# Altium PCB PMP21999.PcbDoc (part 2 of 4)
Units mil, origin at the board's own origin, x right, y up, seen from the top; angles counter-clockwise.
Board outline 7450 x 5800 mil, 6 copper layers (Top Layer, Signal Layer 3, Signal Layer 1, Signal Layer 2, Signal Layer 4, Bottom Layer), stack 66 mil thick; 237 components, 96 nets, 712 pads, 268 vias.
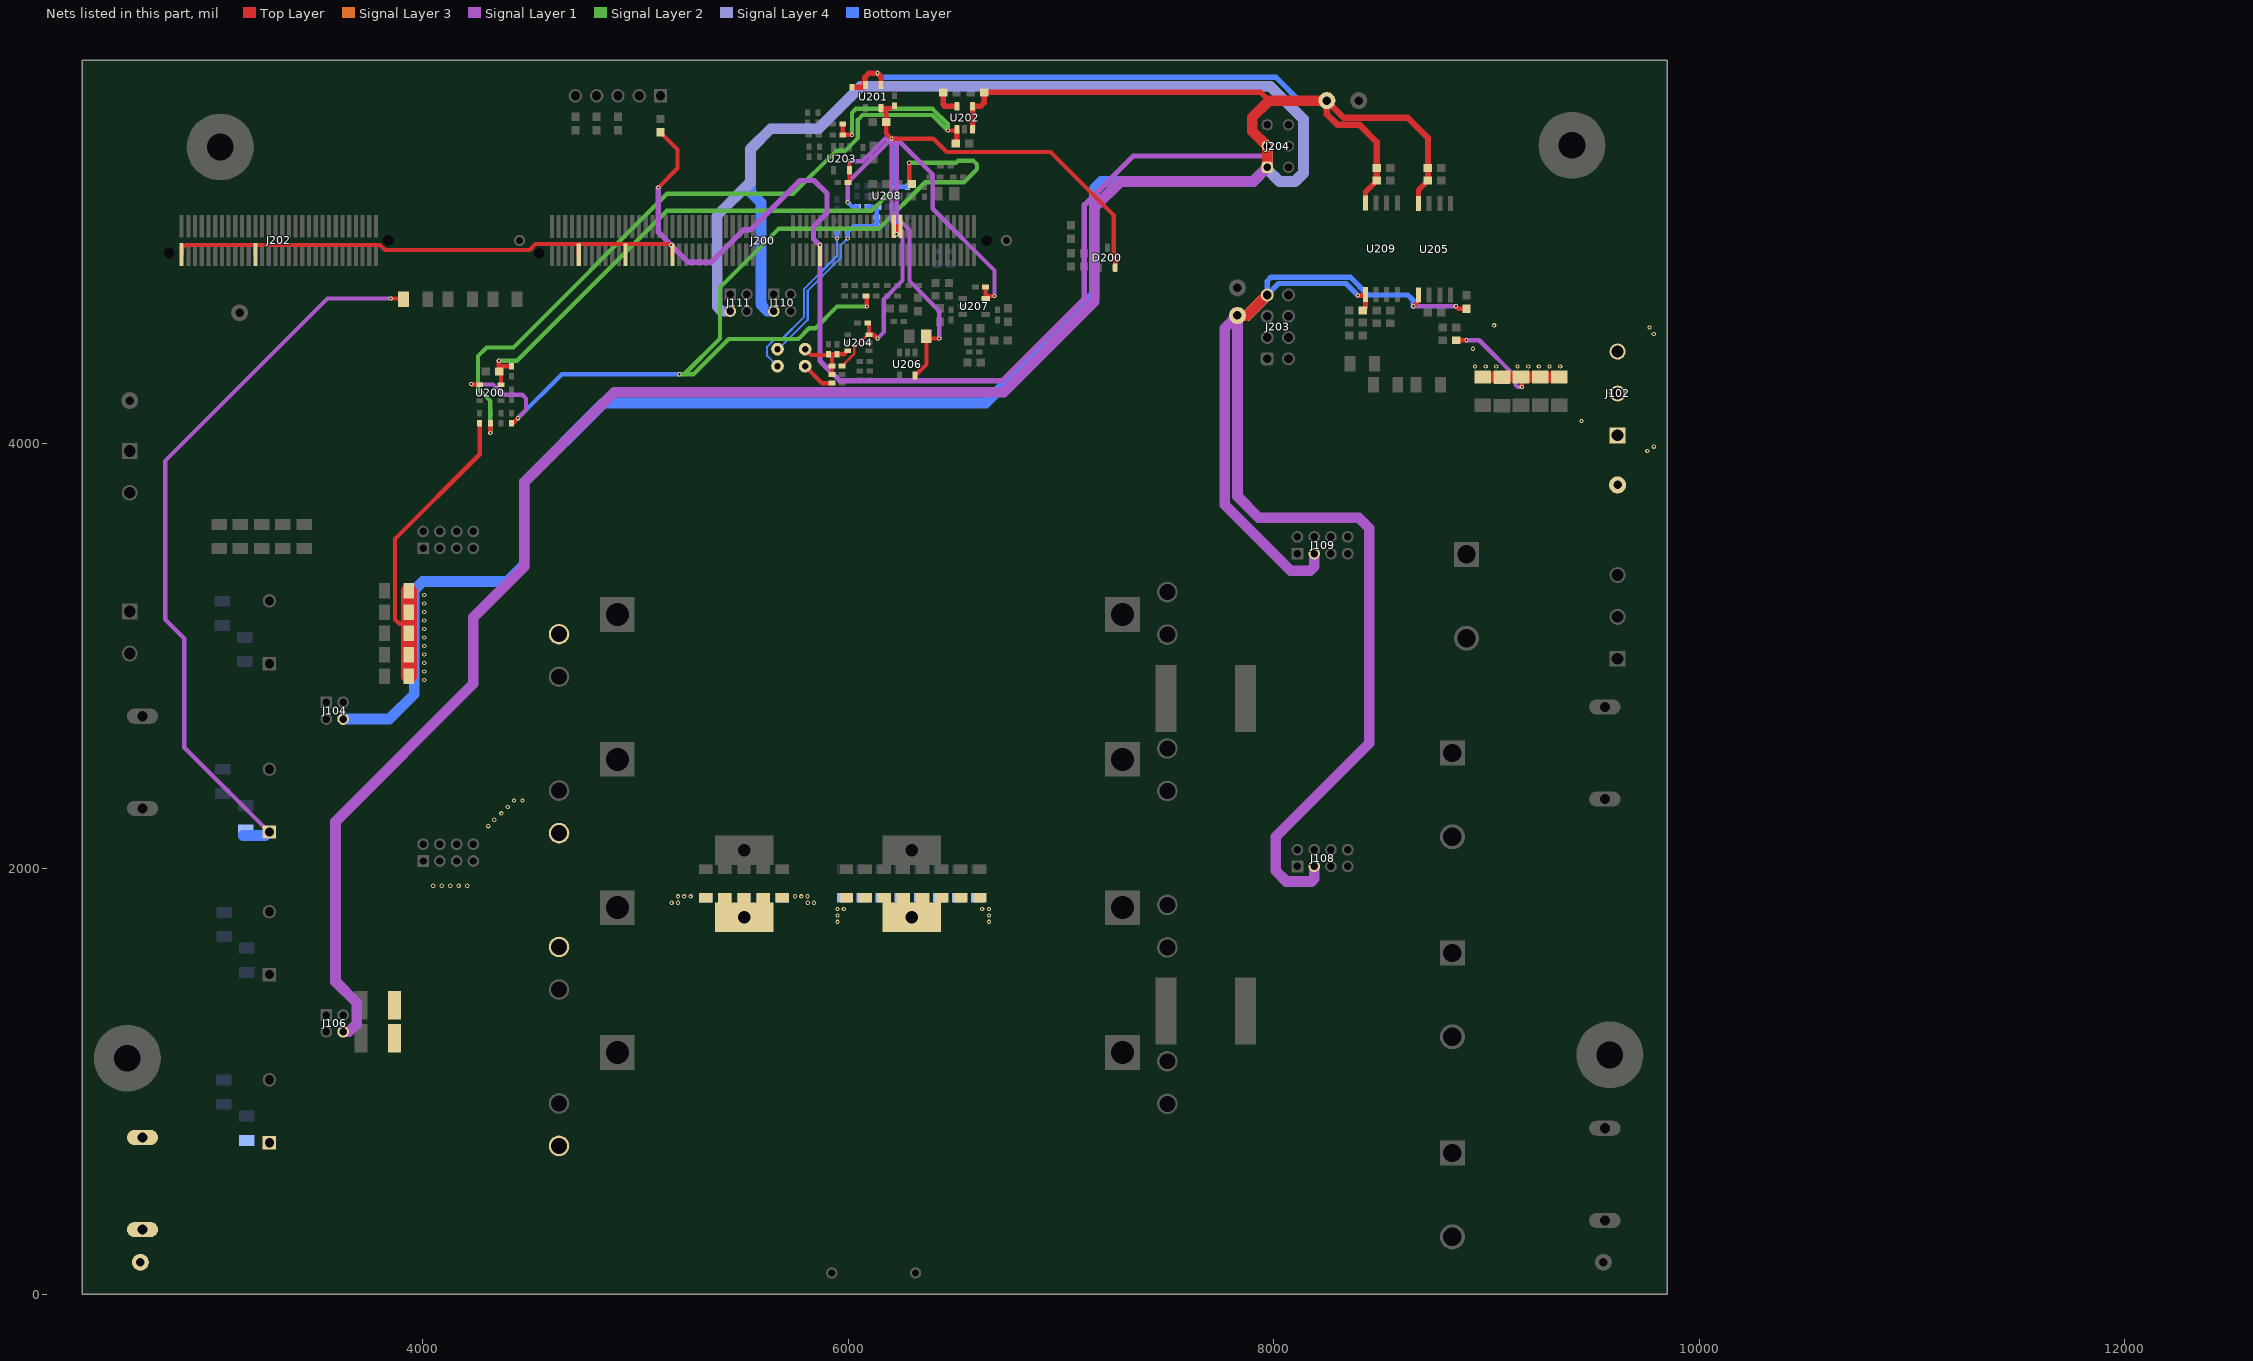
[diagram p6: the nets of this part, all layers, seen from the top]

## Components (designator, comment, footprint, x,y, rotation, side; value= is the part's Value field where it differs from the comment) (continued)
R122 "WSLP1206R0100FEA" 1206 3877.95,3005.51 r0 top value=0.01
R200 "RC0402FR-0756R2L" 0402 6208,4691.87 r180 top value=56.2
R201 "CRCW0402150KFKED" 0402 4418.52,4117.51 r270 top value=150k
R202 "RC0402FR-0756R2L" 0402 6458,5301.87 r180 top value=56.2
R203 "CRCW040210K0FKED" 0402 4418.52,4337.51 r90 top value=10.0k
R204 "CRCW080528K7FKEA" 0805_HV 6458,5171.87 r0 top value=28.7k
R205 "CRCW040210K0FKED" 0402 4268.52,4117.51 r270 top value=10.0k
R206 "CRCW060314K3FKEA" 0603 7048,4991.87 r90 top value=14.3k
R207 "CRCW060325R5FKEA" 0603 6442.41,4692.86 r0 top value=25.5
R208 "CRCW060325R5FKEA" 0603 6328,4651.87 r270 top value=25.5
R209 "RC0402FR-0756R2L" 0402 6518,5251.87 r180 top value=56.2
R210 "CRCW0402150KFKED" 0402 4318.52,4117.51 r90 top value=150k
R211 "CRCW04021K24FKED" 0402 6358,5181.87 r270 top value=1.24k
R212 "CRCW040210K0FKED" 0402 4368.52,4117.51 r90 top value=10.0k
R213 "CRCW040210K0FKED" 0402 4418.52,4227.51 r90 top value=10.0k
R214 "CRCW060356R2FKEA" 0603 6268,5219 r180 top value=56.2
R215 "RC0402FR-0756R2L" 0402 6008,4691.87 r180 top value=56.2
R216 "CRCW06031K00FKEA" 0603 7048,4861.87 r90 top value=1.00k
R217 "RC0402FR-0756R2L" 0402 6108,4691.87 r180 top value=56.2
R218 "CRCW060325R5FKEA" 0603 6148,5219 r180 top value=25.5
R219 "CRCW06030000Z0EA" 0603 5118,5491.87 r270 top value=0
R220 "CRCW06030000Z0EA" 0603 4918,5501.87 r90 top value=0
R221 "CRCW06030000Z0EA" 0603 4818,5501.87 r90 top value=0
R224 "CRCW06030000Z0EA" 0603 4718,5501.87 r90 top value=0
R227 "CRCW06037K15FKEA" 0603 6118.95,5366.13 r90 top value=7.15k
R228 "CRCW04023K65FKED" 0402 6078,4383.53 r180 top value=3.65k
R229 "CRCW040210K0FKED" 0402 5948,4361.87 r0 top value=10.0k
R230 "CRCW04021K00FKED" 0402 5948,4281.87 r0 top value=1.00k
R231 "CRCW04021K00FKED" 0402 6078,4296.87 r0 top value=1.00k
R232 "CRCW060339R2FKEA" 0603 8826.4,4483.54 r180 top value=39.2
R233 "RC0402FR-074K7L" 0402 5808,5529 r270 top value=4.70k
R234 "RC0402FR-074K7L" 0402 5816.35,5369 r270 top value=4.70k
R235 "RC0402FR-074K7L" 0402 5858,5529 r270 top value=4.70k
R236 "RC0402FR-074K7L" 0402 5866.35,5369 r270 top value=4.70k
R237 "CRCW060339R2FKEA" 0603 8826.4,4543.54 r180 top value=39.2
R238 "CRCW04027K15FKED" 0402 5950.87,5449 r180 top value=7.15k
R239 "CRCW040210K0FKED" 0402 5908,4441.87 r270 top value=10.0k
R240 "CRCW1206365KFKEA" 1206 3967.24,4675.42 r180 top value=365k
R241 "RC1206FR-072ML" 1206 8726.4,4273.54 r0 top value=2.00Meg
R242 "CRCW06038K25FKEA" 0603 6752.41,4602.86 r90 top value=8.25k
R243 "CRCW1206365KFKEA" 1206 4177.24,4675.42 r180 top value=365k
R244 "CRCW04023K65FKED" 0402 6088,5183.76 r270 bottom value=3.65k
R245 "RC1206FR-072ML" 1206 8526.4,4273.54 r0 top value=2.00Meg
R246 "CRCW1206365KFKEA" 1206 4387.24,4675.42 r180 top value=365k
R247 "CRCW040210K0FKED" 0402 6068,5111.87 r180 bottom value=10.0k
R248 "CRCW04021K00FKED" 0402 5948,5021.87 r90 bottom value=1.00k
R249 "CRCW04021K00FKED" 0402 5948,5121.87 r90 bottom value=1.00k
R250 "RC1206FR-072ML" 1206 8416.4,4373.54 r0 top value=2.00Meg
R251 "CRCW06030000Z0EA" 0603 8386.4,4566.34 r0 top value=0
R252 "CRCW06032K55FKEA" 0603 6718,4481.87 r180 top value=2.55k
R253 "CRCW06032K55FKEA" 0603 6622.41,4509.1 r90 top value=2.55k
R254 "RC0402FR-0756R2L" 0402 6258,5062.23 r0 bottom value=56.2
R255 "CRCW06035K49FKEA" 0603 6228,4631.87 r180 top value=5.49k
R256 "CRCW06032K55FKEA" 0603 6592.41,4378.6 r180 top value=2.55k
R257 "CRCW06032K55FKEA" 0603 6562.41,4509.1 r90 top value=2.55k
R258 "CRCW060325K5FKEA" 0603 8386.4,4506.34 r180 top value=25.5k
R259 "CRCW06030000Z0EA" 0603 8516.4,4563.54 r180 top value=0
R260 "CRCW06038K25FKEA" 0603 6432.41,4602.86 r270 top value=8.25k
R261 "CRCW040210K0FKED" 0402 6158,5020.06 r180 bottom value=10.0k
T100 "VA-18191B" FP-VA-18191B_XFMR_PTH_8-MFG 6102.36,2165.35 r270 top
TP100 "5000" Keystone5000 2673.46,150 r90 top
TP101 "5000" Keystone5000 9550,150 r90 top
TP102 "5001" Keystone5001 7830,4730 r0 top
TP103 "5001" Keystone5001 9616.4,3803.54 r90 top
TP104 "5001" Keystone5001 2623.46,4200 r90 top
TP105 "5001" Keystone5001 3140,4612.8 r90 top
TP106 "5001" Keystone5001 8400,5610 r0 top
TP200 "5000" Keystone5000 8250,5610 r0 top
TP201 "5000" Keystone5000 7830,4600 r0 top
U200 "LMV116MF" DBV0006A_L 4318.52,4237.51 r0 top
U201 "TLV71333PQDBVRQ1" DBV0005A_N 6118,5629 r270 top
U202 "REF2033AIDDCR" DDC0005A_N 6548,5529 r90 top
U203 "OPA320AIDBVR" DBV0005A_N 5968.95,5336.13 r270 top
U204 "LMV116MF" DBV0006A_L 6048,4471.87 r0 top
U205 "AMC1302QDWVRQ1" DWV0008A 8755.89,4911.57 r90 top
U206 "OPA320AIDBVR" DBV0005A_N 6278,4371.87 r270 top
U207 "OPA320AIDBVR" DBV0005A_N 6592.41,4642.86 r0 top
U208 "LMV116MF" DBV0006A_L 6182.45,5161.87 r90 bottom
U209 "AMC1311BDWVR" DWV0008A 8506.4,4913.54 r90 top
XF100 "1A3400-10" Eaton_1A3400-10 2683.46,2500 r90 top
XF101 "1A3400-10" Eaton_1A3400-10 2683.46,520 r90 top
XF102 "1A3400-10" Eaton_1A3400-10 9556.4,563.54 r270 top
XF103 "1A3400-10" Eaton_1A3400-10 9556.4,2543.54 r270 top

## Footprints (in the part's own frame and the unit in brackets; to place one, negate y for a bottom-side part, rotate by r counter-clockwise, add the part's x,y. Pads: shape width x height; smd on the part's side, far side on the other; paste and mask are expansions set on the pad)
0402 [mm] "0402 from SM-752 data"
  rect 0.8x0.6 smd: 1(-0.6,0) 2(0.6,0)
  silkscreen extent -1.22,-0.52 1.22,0.52, body extent -0.55,-0.3 0.55,0.3, height 0.6
0603 [mm] "0603 from SM-752 data"
  rect 1x0.95 smd: 1(-0.8,0) 2(0.8,0)
  silkscreen extent -1.52,-0.69 1.52,0.69, body extent -0.87,-0.47 0.87,0.47, height 1
0805_HV [mil] "0805 with 30mil clearance between pads"
  rect 50x63 smd: 1(-40,0) 2(40,0)
  silkscreen extent -74,-40 74,40, body extent -43,-29 43,29, height 57
1206 [mm] "1206 from SM-752 data"
  rect 1.3x1.85 smd: 1(-1.45,0) 2(1.45,0)
  silkscreen extent -2.4,-1.21 2.4,1.21, body extent -1.7,-0.9 1.7,0.9, height 1.35
1206_190 [mm] "1206_190"
  rect 1.1x1.6 smd: 1(-1.7,0) 2(1.7,0)
  silkscreen extent -0.9,-1 0.9,1, body extent -1.75,-0.95 1.75,0.95, height 1.9
1812_254 [mm] "SMD, 2-Leads, Body 4.8x3.4mm"
  rect 1.6x3.4 smd: 1(-2,0) 2(2,0)
  silkscreen extent -0.8,-1.7 0.8,1.7, body extent -2.4,-1.7 2.4,1.7, height 2.54
B58031I_1084x785x450 [mm] "SMD, 2-Leads, Body 6.84x7.85mm"
  rect 2.5x8 smd: 1(-4.75,0) 2(4.75,0)
  silkscreen extent -3.2,-3.92 3.2,3.93, body extent -5.67,-4.17 5.67,4.18, height 4.5
CAPRD1000W60D900H1200 [mm] "Disk, Radial Capacitor"
  round 1.35 hole 0.85: 1(-5,0) 2(5,0)
  silkscreen extent -5.3,-3.5 5.3,3.5, body extent -4.48,-3.5 4.48,3.5, height 11.99
controlCARD-120HSEC [mm] "Pads are not numbered according to Samtec datasheet."
  rect 0.5x2.724 smd: 1(-23.357,-1.678) 2(-23.357,1.722) 3(-22.557,-1.678) 4(-22.557,1.722) 5(-21.757,-1.678) 6(-21.757,1.722) 7(-20.957,-1.678) 8(-20.957,1.722) 9(-20.157,-1.678) 10(-20.157,1.722) 11(-19.357,-1.678) 12(-19.357,1.722) 13(-18.557,-1.678) 14(-18.557,1.722) 15(-17.757,-1.678) 16(-17.757,1.722) 17(-16.957,-1.678) 18(-16.957,1.722) 19(-16.157,-1.678) 20(-16.157,1.722) 21(-15.357,-1.678) 22(-15.357,1.722) 23(-14.557,-1.678) 24(-14.557,1.722) 25(-13.757,-1.678) 26(-13.757,1.722) 27(-12.957,-1.678) 28(-12.957,1.722) 29(-12.157,-1.678) 30(-12.157,1.722) 31(-11.357,-1.678) 32(-11.357,1.722) 33(-10.557,-1.678) 34(-10.557,1.722) 35(-9.757,-1.678) 36(-9.757,1.722) 37(-8.957,-1.678) 38(-8.957,1.722) 39(-8.157,-1.678) 40(-8.157,1.722) 41(-7.357,-1.678) 42(-7.357,1.722) 43(-6.557,-1.678) 44(-6.557,1.722) 45(-5.757,-1.678) 46(-5.757,1.722) 47(-4.957,-1.678) 48(-4.957,1.722) 49(-4.157,-1.678) 50(-4.157,1.722) 51(-3.357,-1.678) 52(-3.357,1.722) 53(-2.557,-1.678) 54(-2.557,1.722) 55(-1.757,-1.678) 56(-1.757,1.722) 57(2.243,-1.678) 58(2.243,1.722) 59(3.043,-1.678) 60(3.043,1.722) 61(3.843,-1.678) 62(3.843,1.722) 63(4.643,-1.678) 64(4.643,1.722) 65(5.443,-1.678) 66(5.443,1.722) 67(6.243,-1.678) 68(6.243,1.722) 69(7.043,-1.678) 70(7.043,1.722) 71(7.843,-1.678) 72(7.843,1.722) 73(8.643,-1.678) 74(8.643,1.722) 75(9.443,-1.678) 76(9.443,1.722) 77(10.243,-1.678) 78(10.243,1.722) 79(11.043,-1.678) 80(11.043,1.722) 81(11.843,-1.678) 82(11.843,1.722) 83(12.643,-1.678) 84(12.643,1.722) 85(13.443,-1.678) 86(13.443,1.722) 87(14.243,-1.678) 88(14.243,1.722) 89(15.043,-1.678) 90(15.043,1.722) 91(15.843,-1.678) 92(15.843,1.722) 93(16.643,-1.678) 94(16.643,1.722) 95(17.443,-1.678) 96(17.443,1.722) 97(18.243,-1.678) 98(18.243,1.722) 99(19.043,-1.678) 100(19.043,1.722) 101(19.843,-1.678) 102(19.843,1.722) 103(20.643,-1.678) 104(20.643,1.722) 105(21.443,-1.678) 106(21.443,1.722) 107(22.243,-1.678) 108(22.243,1.722) 109(23.043,-1.678) 110(23.043,1.722) 111(23.843,-1.678) 112(23.843,1.722) 113(24.643,-1.678) 114(24.643,1.722) 115(25.443,-1.678) 116(25.443,1.722) 117(26.243,-1.678) 118(26.243,1.722) 119(27.043,-1.678) 120(27.043,1.722)
  round 0.025 hole 1.27 unplated mask+0.876: 181(-24.857,0.022) 182(28.543,1.522)
  round 1.348 hole 0.84: 185(-27.207,0.022) 186(30.893,0.022)
  silkscreen extent -32.11,-3.86 35.8,3.9, body extent -31.75,-3.48 35.3,3.52, height 12.35
controlCARD-180HSEC-60pinAddon [mm] "Pads are not numbered according to datasheet."
  round 0.025 hole 1.27 unplated mask+0.876: 61(-13.1,0) 62(13.1,1.5)
  rect 0.5x2.724 smd: 121(-11.6,-1.7) 122(-11.6,1.7) 123(-10.8,-1.7) 124(-10.8,1.7) 125(-10,-1.7) 126(-10,1.7) 127(-9.2,-1.7) 128(-9.2,1.7) 129(-8.4,-1.7) 130(-8.4,1.7) 131(-7.6,-1.7) 132(-7.6,1.7) 133(-6.8,-1.7) 134(-6.8,1.7) 135(-6,-1.7) 136(-6,1.7) 137(-5.2,-1.7) 138(-5.2,1.7) 139(-4.4,-1.7) 140(-4.4,1.7) 141(-3.6,-1.7) 142(-3.6,1.7) 143(-2.8,-1.7) 144(-2.8,1.7) 145(-2,-1.7) 146(-2,1.7) 147(-1.2,-1.7) 148(-1.2,1.7) 149(-0.4,-1.7) 150(-0.4,1.7) 151(0.4,-1.7) 152(0.4,1.7) 153(1.2,-1.7) 154(1.2,1.7) 155(2,-1.7) 156(2,1.7) 157(2.8,-1.7) 158(2.8,1.7) 159(3.6,-1.7) 160(3.6,1.7) 161(4.4,-1.7) 162(4.4,1.7) 163(5.2,-1.7) 164(5.2,1.7) 165(6,-1.7) 166(6,1.7) 167(6.8,-1.7) 168(6.8,1.7) 169(7.6,-1.7) 170(7.6,1.7) 171(8.4,-1.7) 172(8.4,1.7) 173(9.2,-1.7) 174(9.2,1.7) 175(10,-1.7) 176(10,1.7) 177(10.8,-1.7) 178(10.8,1.7) 179(11.6,-1.7) 180(11.6,1.7)
  silkscreen extent -14.68,-3.88 14.68,3.88, body extent -14.3,-3.5 14.3,3.5, height 7.95
CSNL1206 [mm] "Stackpole Electronics"
  rrect6% 1.6x2 smd: 1(-1.7,0) 2(1.7,0)
  silkscreen extent -0.63,-1.02 0.63,1.05, body extent -1.72,-0.92 1.72,0.92, height 0.9
DBV0005A_N [mm] "SOT23, 5-Leads, Body 2.9x1.6mm, Pitch 0.95mm, Lead Span 2.8mm, IPC Medium Density"
  rrect17% 1x0.6 smd: 1(-1.375,0.95) 2(-1.375,0) 3(-1.375,-0.95) 4(1.375,-0.95) 5(1.375,0.95)
  silkscreen extent -1.63,-1.55 0.38,1.55, body extent -1.42,-1.46 1.42,1.46, height 1.09
DBV0006A_L [mm] "SOT23, 6-Leads, Body 2.9x1.6mm, Pitch 0.95mm, Lead Span 2.8mm, IPC High Density"
  rrect18% 0.8x0.55 smd: 1(-1.275,0.95) 2(-1.275,0) 3(-1.275,-0.95) 4(1.275,-0.95) 5(1.275,0) 6(1.275,0.95)
  silkscreen extent -1.55,-1.53 0.55,1.53, body extent -1.42,-1.46 1.42,1.46, height 1.12
DDC0005A_N [mm]
  rrect17% 1x0.6 smd: 1(-1.375,0.95) 2(-1.375,0) 3(-1.375,-0.95) 4(1.375,-0.95) 5(1.375,0.95)
  silkscreen extent -1.25,-1.52 0.88,1.57, body extent -1.41,-1.45 1.41,1.45, height 1.1
DWV0008A [mm] "SOIC, 8-Leads, Body 5.95x7.6mm (max), Pitch 1.27mm"
  rrect17% 1.8x0.6 smd: 1(-5.45,1.905) 2(-5.45,0.635) 3(-5.45,-0.635) 4(-5.45,-1.905) 5(5.45,-1.905) 6(5.45,-0.635) 7(5.45,0.635) 8(5.45,1.905)
  silkscreen extent -6.25,-2.95 2.98,2.95, body extent -5.77,-2.92 5.77,2.93, height 2.67
Eaton_1A3400-10 [mm] "TH, 2-Leads, Body 11.1x11.94mm"
  oval 1.8x3.75 hole 1.2 slot 2.5 at 90 deg: 1(-5.5,0) 2(5.5,0)
  body extent -5.85,-6.41 5.85,6.41, height 18.03
FC_1600x4000 [mm] "TH, 2-Leads, Dia 16mm, Pin Spacing 7.5mm"
  rect 1.6x1.6 hole 1.1: 1(-3.75,0)
  round 1.6 hole 1.1: 2(3.75,0)
  silkscreen extent -8.25,-8.25 8.25,8.25, body extent -8.19,-8.24 8.23,8.24, height 42.01
FCC_disclaimer [mil]
FP-MTMM-102-09-G-D-315_HDR4-MFG [mm]
  rrect7% 1.39x1.39 hole 0.89 paste-1000 mask+0: 1(-1,-1)
  round 1.39 hole 0.89 paste-1000 mask+0: 2(-1,1) 3(1,-1) 4(1,1)
  body extent -2.1,-2.09 2.1,2.09, height 0.25
FP-MTMM-104-09-G-D-320_HDR8-MFG [mm]
  rrect7% 1.39x1.39 hole 0.89 paste-1000 mask+0: 1(-3,-1)
  round 1.39 hole 0.89 paste-1000 mask+0: 2(-3,1) 3(-1,-1) 4(-1,1) 5(1,-1) 6(1,1) 7(3,-1) 8(3,1)
  body extent -4.1,-2.13 4.1,2.13, height 0.25
FP-VA-18191B_XFMR_PTH_8-MFG [mm]
  rect 4.15x4.15 hole 2.75 square paste-1000 mask+0: 1(-26.15,-30.15) 2(26.15,-30.15) 3(-8.85,30.15) 4(8.85,30.15) 5(-8.85,-30.15) 6(8.85,-30.15) 7(-26.15,30.15) 8(26.15,30.15)
  body extent -49.6,-33.35 49.6,33.35, height 0.25
IEC_HighVoltage_Medium [mil]
  silkscreen extent -217,-176 217,200
IEC_HotSurface_Medium [mil]
  silkscreen extent -217,-188 217,188
Keystone5000 [mil] "For Keystone 500x miniature loop terminals"
  round 80 hole 40: 1(0,0)
  silkscreen extent -52,-52 52,52, body extent -49,-49 49,49, height 182
Keystone5001 [mil] "For Keystone 500x miniature loop terminals"
  round 80 hole 40: 1(0,0)
  silkscreen extent -52,-52 52,52, body extent -49,-49 49,49, height 182
Keystone_1902C [mil] "Hex Standoff, 4-40 threaded, nylon"
  round 1 on Mech4: 0(0,0)
  body extent -145,-126 146,126, height 501
Mill-Max_0312-0-15-15-34-27-10-0 [mm] "Pin Receptacle, .032-.046\" .075\" Dia, Gold, TH"
  round 2.45 hole 1.905: 1(0,0)
  silkscreen extent -1.52,-1.52 1.52,1.52, body extent -1.15,-1.15 1.16,1.15, height 0.46
Nichicon_2200x4500_Snap [mm]
  rrect3% 3x3 hole 2.2: 1(-5,0)
  round 3 hole 2.2: 2(5,0)
  silkscreen extent -11.6,-11.6 11.6,11.6, body extent -11.5,-11.49 11.51,11.49, height 47.01
"NY PMS 440 0025 PH" [mm] "4-40 nylon screw and mounting hole"
  round 8 hole 3.2: 1(0,0)
  body extent -3.3,-3.3 3.3,3.3, height 2.69
Pb-Free_Overlay_Medium [mil]
  silkscreen extent -95,-95 95,95
Samtec_SSW-104-24-x-D [mm] "Receptacle, 2.54mm, 4x2, TH"
  rrect50% 1.55x1.55 hole 1.04: 1(-3.81,1.27)
  round 1.55 hole 1.04: 2(-3.81,-1.27) 3(-1.27,1.27) 4(-1.27,-1.27) 5(1.27,1.27) 6(1.27,-1.27) 7(3.81,1.27) 8(3.81,-1.27)
  silkscreen extent -5.43,-2.58 5.43,3, body extent -5.33,-2.48 5.33,2.48, height 8.51
SOT-23 [mm] "SOT23, 3-Leads, Body 2.9x1.3mm, Pitch 0.95mm, Lead Span 2.5mm, IPC Medium Density"
  rrect50% 1x0.6 smd: 1(-1.2,0.95) 2(-1.2,-0.95) 3(1.2,0)
  silkscreen extent -1.62,-1.5 0.7,1.5, body extent -1.16,-1.45 1.21,1.45, height 1
TE_215307-3 [mm] "Receptacle, 2.54mm, 3x2, TH"
  rrect50% 1.35x1.35 hole 0.9: 1(-2.54,1.27)
  round 1.35 hole 0.9: 2(-2.54,-1.27) 3(0,1.27) 4(0,-1.27) 5(2.54,1.27) 6(2.54,-1.27)
  body extent -3.81,-2.53 3.81,2.53, height 7
TE_282856-2 [mm] "TH, 2-Leads, Body 10x10mm, Pitch 5mm"
  rect 1.9x1.9 hole 1.4: 1(-2.5,0)
  round 1.9 hole 1.4: 2(2.5,0)
  silkscreen extent -5.61,-5 5.5,5, body extent -5,-5 5.5,5, height 19
TE_282856-3 [mm] "Receptacle, 3x1, 5mm, R/A, TH"
  rect 1.9x1.9 hole 1.4: 1(-5,0)
  round 1.9 hole 1.4: 2(0,0) 3(5,0)
  silkscreen extent -8,-5 8,5, body extent -7.5,-5 8,5, height 19
WEEE_Minimum [mil] "WEEElie bin"
  silkscreen extent -95,-172 99,104
Wurth_61300511021 [mm] "Header, 2.54 mm, 5x1, R/A, TH"
  rect 1.6x1.6 hole 1.1: 1(-5.08,0)
  round 1.6 hole 1.1: 2(-2.54,0) 3(0,0) 4(2.54,0) 5(5.08,0)
  silkscreen extent -6.75,-4.04 6.35,-1.5, body extent -6.35,-10.04 6.35,0.32, height 2.55

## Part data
C100 C105 C108 C109 C110 C113 C114 C115 C122 C126 C127 C128 C129 C130 C131 C132 C133 C134 C135 C136 C137 C138 C139 C141 C143 C145: library part CMP-0008795-2, "CAP CER 8200PF 630V NP0 1206", Cap_Case=1206, Manufacturer=TDK, PartNumber=CGA5L4NP02J822J160AA, TempCo=C0G, Tolerance_%=5%, Value1=Unknown, Value2=630V, ValueDisplayed=8200pF
C101 C102 C111 C112: library part EEU-FC2A471, "CAP ALUM 150UF 20% 400V RADIAL", Cap_Case=16x40mm, Manufacturer=Rubycon, Tolerance_%=20, Value2=400V, ValueDisplayed=150µF
C103 C104 C106 C107: library part LLS2G221MELZ, "CAP ALUM 150UF 20% 500V SNAP", Cap_Case=22x45mm, Manufacturer=Rubycon, Tolerance_%=20, Value2=500V, ValueDisplayed=150µF
C120: library part C1812W104KDRACTU, "CAP, CERM, 0.1 µF, 1000 V,+/- 10%, X7R, 1812", Cap_Case=1812, Manufacturer="Knowles Syfer", TempCo=X7R, Tolerance_%=10, Value2=1000V, ValueDisplayed=0.1µF
C121: library part C1812W104KDRACTU, "CAP CER 0.1UF 1KV X7R 1812", Cap_Case=1812, Manufacturer="Knowles Syfer", TempCo=X7R, Tolerance_%=10, Value2=1000V, ValueDisplayed=0.1µF
C123 C124: library part CMP-0009311-2, "CAP, CERM, 1 uF, 500 V, +/- 20%, B58031, AEC-Q200 Grade 0, 6.84x7.85mm", Cap_Case=10.84x7.85x4.5mm, Manufacturer=TDK, PartNumber=B58031I5105M062, TempCo=B58031, Tolerance_%=20%, Value1=Unknown, Value2=500V, ValueDisplayed=1uF
C147: "CAP, CERM, 2200 pF, 250 V, +/- 20%, E, Cap, 7x12x9 mm", Cap_Case=CAPRD1000W60D900H1200, Manufacturer=MuRata, Supplier Part Number 1=490-7047-ND, TempCo=E, Tolerance_%=20, Value1=Unknown, Value2=250V, ValueDisplayed=2200pF
C200 C210 C211 C246: "CAP, CERM, 10 pF, 10 V,+/- 2.5%, C0G/NP0, 0402", Cap_Case=0402, Manufacturer=Kemet, Supplier Part Number 1=399-8939-1-ND, TempCo=C0G/NP0, Tolerance_%=2.5, Value2=10V, ValueDisplayed=10pF
C201 C205 C206 C209 C216 C218 C219 C224 C237: "CAP, CERM, 0.1uF, 25V, +/-5%, X7R, 0603", Cap_Case=0603, Manufacturer=AVX, Supplier Part Number 1=478-3713-1-ND, TempCo=X7R, Tolerance_%=5, Value1="0.05 ohm", Value2=25V, ValueDisplayed=0.1µF
C202: "CAP, CERM, 2.2 µF, 6.3 V,+/- 10%, X6S, 0603", Cap_Case=0603, Manufacturer=MuRata, Supplier Part Number 1=GRM188C80J225KE19D-ND, TempCo=X6S, Tolerance_%=10, Value2=6.3V, ValueDisplayed=2.2µF
C203: library part GRM155R60J222KA01D, "CAP CER 2200PF 6.3V X7R 0402", Cap_Case=0402, Manufacturer=KEMET, TempCo=X7R, Tolerance_%=10, Value2=6.3V, ValueDisplayed=2200pF
C204: library part GRM1555C1H221JA01D, "CAP, CERM, 220 pF, 50 V,+/- 5%, C0G/NP0, 0402", Cap_Case=0402, Manufacturer=Yageo, TempCo=C0G/NP0, Tolerance_%=5, Value2=50V, ValueDisplayed=220pF
C207 C225 C238: "CAP, CERM, 0.1 µF, 25 V,+/- 20%, X7R, 0402", Cap_Case=0402, Manufacturer=TDK, Supplier Part Number 1=445-7349-1-ND, TempCo=X7R, Tolerance_%=20, Value2=25V, ValueDisplayed=0.1µF
C208: "CAP, CERM, 10 pF, 50 V,+/- 5%, C0G/NP0, 0603", Cap_Case=0603, Manufacturer=Kemet, Supplier Part Number 1=399-1049-1-ND, TempCo=C0G/NP0, Tolerance_%=5, Value2=50V, ValueDisplayed=10pF
C214 C222 C235: "CAP, CERM, 1uF, 25V, +/-10%, X7R, 0603", Cap_Case=0603, Manufacturer=TDK, Supplier Part Number 1=445-5956-1-ND, TempCo=X7R, Tolerance_%=10, Value1=Unknown, Value2=25V, ValueDisplayed=1uF
C215 C217: library part GRM155R70J104KA01D, "CAP, CERM, 0.1uF, 6.3V, +/-10%, X7R, 0402", Cap_Case=0402, Manufacturer=Yageo, TempCo=X7R, Tolerance_%=10, Value1=Unknown, Value2=6.3V, ValueDisplayed=0.1uF
C220 C229 C230 C232 C243 C244: "CAP, CERM, 0.01 µF, 10 V,+/- 10%, X5R, 0402", Cap_Case=0402, Manufacturer=MuRata, Supplier Part Number 1=GRM155R61A103KA01D-ND, TempCo=X5R, Tolerance_%=10, Value2=10V, ValueDisplayed=0.01µF
C221 C233: "CAP, CERM, 2.2 pF, 50 V,+/- 5%, C0G/NP0, 0402", Cap_Case=0402, Manufacturer=MuRata, Supplier Part Number 1=490-6227-1-ND, TempCo=C0G/NP0, Tolerance_%=5, Value2=50V, ValueDisplayed=2.2pF
C223 C236: "CAP, CERM, 4.7 µF, 10 V,+/- 10%, X5R, 0603", Cap_Case=0603, Manufacturer=TDK, Supplier Part Number 1=445-7482-1-ND, TempCo=X5R, Tolerance_%=10, Value2=10V, ValueDisplayed=4.7µF
C226 C231 C239 C245: "CAP, CERM, 0.1 µF, 16 V,+/- 10%, X7R, 0402", Cap_Case=0402, Manufacturer=AVX, Supplier Part Number 1=478-7888-1-ND, TempCo=X7R, Tolerance_%=10, Value2=16V, ValueDisplayed=0.1µF
C227 C240: "CAP, CERM, 2200 pF, 50 V,+/- 10%, X7R, AEC-Q200 Grade 1, 0402", Cap_Case=0402, Manufacturer=TDK, Supplier Part Number 1=445-5606-1-ND, TempCo=X7R, Tolerance_%=10, Value1="1.07794 ohm", Value2=50V, ValueDisplayed=2200pF
C228 C242: "CAP, CERM, 0.01 µF, 100 V,+/- 10%, X7R, 0603", Cap_Case=0603, Manufacturer=AVX, Supplier Part Number 1=478-1205-1-ND, TempCo=X7R, Tolerance_%=10, Value1="0.098 ohm", Value2=100V, ValueDisplayed=0.01µF
C234: "CAP, CERM, 0.1 µF, 25 V,+/- 5%, X7R, 0805", Cap_Case=0805, Manufacturer=AVX, Supplier Part Number 1=478-7946-1-ND, TempCo=X7R, Tolerance_%=5, Value2=25V, ValueDisplayed=0.1µF
C241: "CAP, CERM, 470 pF, 50 V,+/- 10%, X7R, AEC-Q200 Grade 1, 0402", Cap_Case=0402, Manufacturer=TDK, Supplier Part Number 1=445-6888-1-ND, TempCo=X7R, Tolerance_%=10, Value1="4.96489 ohm", Value2=50V, ValueDisplayed=470pF
D200: library part CMP-0028456-1, "Diode, Schottky, 30 V, 0.2 A, SOT-23", Manufacturer="Diodes Inc.", Supplier Part Number 1=BAT54S-FDICT-ND, Value1=0.2A, Value2=0.65V
H200 H202 H204 H206: library part CMP-0003610-1, "Standoff, Hex, 0.5\"L #4-40 Nylon", Manufacturer=Keystone, Supplier Part Number 1=36-1902C-ND
H201 H203 H205 H207: library part CMP-0003617-1, "Machine Screw, Round, #4-40 x 1/4, Nylon, Philips panhead", Manufacturer="B&F Fastener Supply", Supplier Part Number 1=H542-ND
J100 J103: library part CMP-0054978-1, "Therminal Block, 5 mm, 2-pole, Tin, TH", Manufacturer="On Shore Technology Inc.", PartNumber=ED700/2
J101 J102: library part CMP-0054983-1, "Receptacle, 3x1, 5mm, R/A, TH", Color=Green, Current_A=24A, Manufacturer="On Shore Technology Inc.", PartNumber=ED700/3, Voltage_V=300V
J104 J106: library part CMP-0087195-1, "Conn Unshrouded Header HDR 4 POS 2mm Solder ST Thru-Hole", Manufacturer=Samtec
J105 J107 J108 J109: library part CMP-0087215-1, "Conn Unshrouded Header HDR 8 POS 2mm Solder ST Thru-Hole", Manufacturer=Samtec
J110 J111: library part CMP-0087195-1, "Conn Unshrouded Header HDR 4 POS 2mm Solder ST Thru-Hole", Manufacturer=Samtec, PartNumber=MTMM-102-04-G-D-148
J200: library part controlCARD-120HSEC, "C2000 controlCARD-120HSEC connector, SMT", Manufacturer=Samtec
J201: library part CMP-0054800-1, "Header, 2.54 mm, 5x1, Gold, R/A, TH", Color=Black, Manufacturer="Wurth Elektronik", Supplier Part Number 1=732-5338-ND
J202: library part CMP-0003859-2, "C2000 controlCARD-180HSEC (60-pin addon) connector, SMT", Manufacturer=Samtec
J203: library part CMP-0055706-1, "Receptacle, 2.54mm, 4x2, Gold, TH", Color=Black, Current_A=4.7A, Manufacturer=Samtec, Voltage_V=465V
J204: library part CMP-0082603-1, "Receptacle, 2.54mm, 3x2, Tin, TH", Color=Green, Manufacturer="TE Connectivity", Supplier Part Number 1=A106656-ND
LOGO100: library part IEC_HotSurface, "IEC 61010-1 Hot Surface Warning"
Logo101: library part CMP-0074839-1
Logo102: library part CMP-0074847-1, "FCC_disclaimer"
Logo103: library part CMP-0074769-1
LOGO104 LOGO105: library part IEC_HighVoltage, "IEC 61010-1 High Voltage Warning"
QPL1H_D QPL1H_S QPL1L_D QPL1L_S QPL2H_D QPL2H_S QPL2L_D QPL2L_S QSL1H_D QSL1H_S QSL1L_D QSL1L_S QSL2H_D QSL2H_S QSL2L_D QSL2L_S: library part 0312-0-15-15-34-27-10-0, "Pin Receptacle, .032-.046\" .075\" Dia, Gold, TH", Manufacturer=Mill-Max, Supplier Part Number 1=0312-015153427100-ND
R100 R101 R105 R106 R110 R111 R114 R115: "RES, 1.00 M, 1%, 0.25 W, 1206", Manufacturer=Vishay-Dale, Power_W=0.25, Supplier Part Number 1=541-1.00MFCT-ND, TempCo="100 ppm/C", Tolerance_%=1, Value1=1%, Value2=0.25W, Value_Code=1M00, ValueDisplayed=1.00M
R102 R104 R108 R112 R116: library part CSNL1206FT5L00, "RES 0.006 OHM 1% 1W 1206", Manufacturer="Rohm Semiconductor", Power_W=1, TempCo="50 ppm/C", Value1=1%, Value2=1W, ValueDisplayed=0.006
R103 R107 R109 R113 R117 R118 R119 R120 R121 R122: library part CMP-0018570-2, "RES, 0.01, 1%, 1 W, 1206", Manufacturer=Vishay-Dale, Power_W=1W, Supplier Part Number 1=WSLP-.01CT-ND, TempCo="75 ppm/C", Tolerance_%=1%, Value_Code=R010, ValueDisplayed=0.01
R200 R202 R209 R215 R217 R254: library part CRCW040256R2FKED, "RES SMD 56.2 OHM 1% 1/16W 0402", Manufacturer=Yageo, Power_W=0.063, TempCo="100 ppm/C", Tolerance_%=1, Value1=1%, Value2=0.063W, Value_Code=56R2, ValueDisplayed=56.2
R201 R210: "RES, 150 k, 1%, 0.063 W, 0402", Manufacturer=Vishay-Dale, Power_W=0.063, Supplier Part Number 1=541-150KLCT-ND, TempCo="100 ppm/C", Tolerance_%=1, Value1=1%, Value2=0.063W, Value_Code=150k
R203 R205 R212 R213 R229 R239 R247 R261: "RES, 10.0 k, 1%, 0.063 W, 0402", Manufacturer=Vishay-Dale, Power_W=0.063, Supplier Part Number 1=541-10.0KLCT-ND, TempCo="100 ppm/C", Tolerance_%=1, Value1=1%, Value2=0.063W, Value_Code=10k0, ValueDisplayed=10.0k
R204: "RES, 28.7 k, 1%, 0.125 W, 0805", Manufacturer=Vishay-Dale, Power_W=0.125, Supplier Part Number 1=541-28.7KCCT-ND, TempCo="100 ppm/C", Tolerance_%=1, Value1=1%, Value2=0.125W, Value_Code=28k7, ValueDisplayed=28.7k
R206: "RES, 14.3 k, 1%, 0.1 W, 0603", Manufacturer=Vishay-Dale, Power_W=0.1, Supplier Part Number 1=541-14.3KHCT-ND, TempCo="100 ppm/C", Tolerance_%=1, Value1=1%, Value2=0.1W, Value_Code=14k3, ValueDisplayed=14.3k
R207 R218: library part CMP-0022243-4, "RES, 25.5, 1%, 0.1 W, AEC-Q200 Grade 0, 0603", Manufacturer=Vishay-Dale, Power_W=100mW, Supplier Part Number 1=541-25.5HCT-ND, TempCo="100 ppm/C", Tolerance_%=1%, Value2=0.1W, Value_Code=25R5, ValueDisplayed=25.5
R208: "RES, 25.5, 1%, 0.1 W, 0603", Manufacturer=Vishay-Dale, Power_W=0.1, Supplier Part Number 1=541-25.5HCT-ND, TempCo="100 ppm/C", Tolerance_%=1, Value1=1%, Value2=0.1W, Value_Code=25R5, ValueDisplayed=25.5
R211: "RES, 1.24 k, 1%, 0.063 W, 0402", Manufacturer=Vishay-Dale, Power_W=0.063, Supplier Part Number 1=541-1.24KLCT-ND, TempCo="100 ppm/C", Tolerance_%=1, Value1=1%, Value2=0.063W, Value_Code=1k24, ValueDisplayed=1.24k
R214: "RES, 56.2, 1%, 0.1 W, 0603", Manufacturer=Vishay-Dale, Power_W=0.1, Supplier Part Number 1=541-56.2HCT-ND, TempCo="100 ppm/C", Tolerance_%=1, Value1=1%, Value2=0.1W, Value_Code=56R2, ValueDisplayed=56.2
R216: "RES, 1.00 k, 1%, 0.1 W, 0603", Manufacturer=Vishay-Dale, Power_W=0.1, Supplier Part Number 1=541-1.00KHCT-ND, TempCo="100 ppm/C", Tolerance_%=1, Value1=1%, Value2=0.1W, Value_Code=1k00, ValueDisplayed=1.00k
R219 R220 R221 R224 R251 R259: "RES, 0, 5%, 0.1 W, 0603", Manufacturer=Vishay-Dale, Power_W=0.1, Supplier Part Number 1=541-0.0GCT-ND, TempCo="200 ppm/C", Tolerance_%=5, Value1=5%, Value2=0.1W, Value_Code=0000, ValueDisplayed=0
R227: library part CMP-0022599-4, "RES, 7.15 k, 1%, 0.1 W, AEC-Q200 Grade 0, 0603", Manufacturer=Vishay-Dale, Power_W=100mW, Supplier Part Number 1=541-7.15KHCT-ND, TempCo="100 ppm/C", Tolerance_%=1%, Value2=0.1W, Value_Code=7k15, ValueDisplayed=7.15k
R228 R244: "RES, 3.65 k, 1%, 0.063 W, 0402", Manufacturer=Vishay-Dale, Power_W=0.063, Supplier Part Number 1=541-3.65KLCT-ND, TempCo="100 ppm/C", Tolerance_%=1, Value1=1%, Value2=0.063W, Value_Code=3k65, ValueDisplayed=3.65k
R230 R231 R248 R249: "RES, 1.00 k, 1%, 0.063 W, 0402", Manufacturer=Vishay-Dale, Power_W=0.063, Supplier Part Number 1=541-1.00KLCT-ND, TempCo="100 ppm/C", Tolerance_%=1, Value1=1%, Value2=0.063W, Value_Code=1k00, ValueDisplayed=1.00k
R232 R237: "RES, 39.2, 1%, 0.1 W, 0603", Manufacturer=Vishay-Dale, Power_W=0.1, Supplier Part Number 1=541-39.2HCT-ND, TempCo="100 ppm/C", Tolerance_%=1, Value1=1%, Value2=0.1W, Value_Code=39R2, ValueDisplayed=39.2
R233 R234 R235 R236: library part CMP-0026739-1, "RES, 4.70 k, 1%, 0.0625 W, 0402", Manufacturer="Yageo America", Power_W=62.5mW, Supplier Part Number 1=311-4.7KLRCT-ND, TempCo="100 ppm/C", Tolerance_%=1%, Value2=0.0625W, Value_Code=4k70, ValueDisplayed=4.70k
R238: "RES, 7.15 k, 1%, 0.063 W, 0402", Manufacturer=Vishay-Dale, Power_W=0.063, Supplier Part Number 1=541-7.15KLCT-ND, TempCo="100 ppm/C", Tolerance_%=1, Value1=1%, Value2=0.063W, Value_Code=7k15, ValueDisplayed=7.15k
R240 R243 R246: library part CMP-0016927-3, "RES, 365 k, 1%, 0.25 W, AEC-Q200 Grade 0, 1206", Manufacturer=Vishay-Dale, Power_W=250mW, Supplier Part Number 1=541-365KFCT-ND, TempCo="100 ppm/C", Tolerance_%=1%, Value2=0.25W, Value_Code=365k
R241 R245 R250: "RES, 2.00 M, 1%, 0.25 W, 1206", Manufacturer="Yageo America", Power_W=0.25, Supplier Part Number 1=311-2.00MFRCT-ND, TempCo="100 ppm/C", Tolerance_%=1, Value1=1%, Value2=0.25W, Value_Code=2M00, ValueDisplayed=2.00M
R242 R260: library part CMP-0022635-4, "RES, 8.25 k, 1%, 0.1 W, AEC-Q200 Grade 0, 0603", Manufacturer=Vishay-Dale, Power_W=100mW, Supplier Part Number 1=541-8.25KHCT-ND, TempCo="100 ppm/C", Tolerance_%=1%, Value2=0.1W, Value_Code=8k25, ValueDisplayed=8.25k
R252 R253 R256 R257: library part CMP-0022278-4, "RES, 2.55 k, 1%, 0.1 W, AEC-Q200 Grade 0, 0603", Manufacturer=Vishay-Dale, Power_W=100mW, Supplier Part Number 1=541-2.55KHCT-ND, TempCo="100 ppm/C", Tolerance_%=1%, Value2=0.1W, Value_Code=2k55, ValueDisplayed=2.55k
R255: library part CMP-0022512-4, "RES, 5.49 k, 1%, 0.1 W, AEC-Q200 Grade 0, 0603", Manufacturer=Vishay-Dale, Power_W=100mW, Supplier Part Number 1=541-5.49KHCT-ND, TempCo="100 ppm/C", Tolerance_%=1%, Value2=0.1W, Value_Code=5k49, ValueDisplayed=5.49k
R258: library part CMP-0022242-4, "RES, 25.5 k, 1%, 0.1 W, AEC-Q200 Grade 0, 0603", Manufacturer=Vishay-Dale, Power_W=100mW, Supplier Part Number 1=541-25.5KHCT-ND, TempCo="100 ppm/C", Tolerance_%=1%, Value2=0.1W, Value_Code=25k5, ValueDisplayed=25.5k
T100: library part CMP-0086457-1, "LLC Transformer", Manufacturer=Cyntec
TP100 TP101 TP200 TP201: "Test Point, Miniature, Red, TH", Color=Red, Manufacturer=Keystone, Supplier Part Number 1=36-5000-ND
TP102 TP103 TP104 TP105 TP106: "Test Point, Miniature, Black, TH", Color=Black, Manufacturer=Keystone, Supplier Part Number 1=36-5001-ND
U200 U204 U208: library part CMP-0040149-1, "IC OPAMP VFB 45MHZ RRO SOT23-5", Manufacturer="Texas Instruments", PartNumber=LMV116MF/NOPB
U201: "Capacitor-Free, 150-mA, Low-Dropout Regulator with Foldback Current Limit for Portable Devices, DBV0005A", Alternate Manufacturer="Texas Instruments"
U202: library part CMP-0066190-1, "Low-Drift, Low-Power, Dual-Output VREF and VREF/2 Voltage Reference, DDC0005A (SOT-23-T-5)", Alternate Manufacturer="Texas Instruments", Alternate PartNumber=REF2033AIDDCT
U203 U206 U207: library part CMP-0040888-1, "Precision, 20 MHz, 0.9 pA Ib, RRIO, CMOS Operational Amplifier, 1.8 to 5.5 V, -40 to 125 degC, 5-pin SOT23 (DBV5), Green (RoHS & no Sb/Br)", Manufacturer="Texas Instruments", Total Supply Voltage(Max)(+5V is 5, +/-5V is 10)=5.5, Total Supply Voltage(Min)(+5V is 5, +/-5V is 10)=1.8
U205: library part CMP-0080587-1, "Precision Reinforced Isolated Amplifier for Current Sensing, DWV0008A (SOIC-8)", Alternate Manufacturer="Texas Instruments"
U209: library part CMP-0078341-1, "Precision, 2-V Input, Reinforced Isolated Amplifier, DWV0008A (SOIC-8)", Alternate Manufacturer="Texas Instruments", Alternate PartNumber=AMC1311BDWV
XF100 XF101 XF102 XF103: library part CMP-0082116-2, "FUSE CLIP CARTRIDGE 30A PCB", Manufacturer=Eaton, PartNumber=BK/1A3400-10

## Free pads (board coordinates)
  rect 275.59x137.8 hole 59.06 square: 1(5511.81,1771.65) 1(5511.81,2086.61) 1(6299.21,1771.65) 1(6299.21,2086.61)
  round 60 hole 30: 1(5798,4361.87) 2(5798,4441.87) 3(5668,4361.87) 4(5668,4441.87)

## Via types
v1: diameter 20, hole 10, Top Layer to Bottom Layer, 268 vias

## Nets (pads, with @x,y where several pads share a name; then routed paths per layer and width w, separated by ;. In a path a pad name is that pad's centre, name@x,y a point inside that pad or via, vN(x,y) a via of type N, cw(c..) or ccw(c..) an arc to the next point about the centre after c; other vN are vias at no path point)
1V65: C219.2 C230.2 R210.1 R238.1 U202.1 | length 4002.7
  Top Layer w20: v1(4318.52,4047.51) R210.1@4318.52,4093.89 ; C230.2@5974.49,5499 R238.1@5974.49,5449 v1(6018,5449) ; v1(6468,5469) U202.1@6504.74,5469
  Top Layer w25: C219.2@6510.6,5413.09 U202.1@6510.6,5474.87
  Signal Layer 2 w20: v1(4318.52,4047.51) 4318.52,4197.49 4271.7,4244.32 4271.7,4244.92 4260.65,4255.96 4260.65,4409.06 4301.59,4450 4426.94,4450 5148.81,5171.87 5740.88,5171.87 5942.85,5373.85 5984.86,5373.85 6045.72,5434.71 6045.72,5519.59 6068,5541.87 6395.13,5541.87 v1(6468,5469) 6468,5500.33 6397.21,5571.13 6035.92,5571.13 6018,5553.21 v1(6018,5449)
3V3: C201.2 C214.2 C215.1 C225.1 C226.1 C234.1 C238.1 C239.1 D200.2 R203.2 R229.2 R247.2 U200.6 U201.5 U203.5 U204.6 U206.5 U207.5 U208.6 | length 8935.8
  Top Layer w12: R229.2@5971.63,4361.87 6028,4418.25 6028,4446.73 6090.55,4509.28 U204.6@6098.2,4509.28
  Top Layer w20: C201.2@4358.52,4339.01 v1(4358.52,4387.51) ; 4360.65,4361.13 R203.2@4418.52,4361.13 ; U200.6@4368.72,4274.91 C201.2@4368.72,4328.81 ; C225.1@6006.35,5233.53 U203.5@6006.35,5282 v1(6006.35,5324.64) ; C226.1@6098.2,4558.17 U204.6@6098.2,4509.28 6120.6,4509.28 v1(6138,4491.87) ; U201.5@6155.41,5574.87 6207.49,5574.87 C215.1@6218,5585.38 ; 6179.5,5572.92 C214.2@6179.5,5509 6179.5,5455.09 v1(6203.59,5431) 6400.62,5431 6463.59,5368.02 6951.86,5368.02 7248,5071.87 7248,4881.87 7255.41,4874.47 D200.2@7255.41,4824.63 ; U206.5@6315.41,4317.74 6368,4370.34 C234.1@6368,4501.87 ; C234.1@6378,4491.87 v1(6428,4491.87) ; C238.1@6646.55,4732.34 6646.55,4691.87 v1(6688,4691.87)
  Signal Layer 1 w20: v1(5998,5131.87) 5998,5225.41 v1(6203.59,5431) ; v1(6006.35,5324.64) 6066.98,5324.64 6173.34,5431 v1(6203.59,5431) ; v1(6138,4491.87) 6168.02,4521.89 6168.02,4676.14 6255.88,4764 6255.88,4993.42 6203.59,5045.7 v1(6203.59,5431) ; v1(6428,4491.87) 6428,4621.87 6288,4761.87 6288,5001.87 6228,5061.87 6228,5406.59 v1(6203.59,5431) ; v1(6688,4691.87) 6688,4811.87 6398,5101.87 6398,5261.87 6228.88,5431 v1(6203.59,5431)
  Signal Layer 2 w20: v1(4358.52,4387.51) 4443.29,4387.51 5147.65,5091.87 6109.74,5091.87 6203.59,5185.72 v1(6203.59,5431)
  Bottom Layer w20: v1(5998,5131.87) 6018,5111.87 R247.2@6044.38,5111.87 ; v1(6203.59,5431) 6219.85,5414.74 U208.6@6219.85,5212.07 6226.43,5205.5 C239.1@6278,5205.5
3V3ref: C218.2 U202.5 | length 125.6
  Top Layer w25: C218.2@6446.51,5649 6446.51,5590.5 6453.87,5583.13 U202.5@6510.6,5583.13
5Vp: C216.2 C217.1 C223.1 C224.2 C236.1 C237.2 J104.4 J106.4 J110.2 J111.2 J200.48 J200.84 J200.98 J200.112 J202.158 J202.180 J204.1 J204.3 R219.2 TP200.1 U201.1 U201.3 U202.3 U202.4 U205.8 U209.8 | length 36307.2
  Top Layer w20: J202.180@2867.57,4885.93 2867.57,4913.17 2886.27,4931.87 3800.36,4931.87 3824.65,4907.58 4503.71,4907.58 4505.8,4909.67 4505.8,4910.7 4530.91,4935.81 5164.06,4935.81 v1(5168,4931.87) 5174.66,4925.22 J200.84@5174.66,4885.06 ; J202.158@3214.03,4885.93 J202.158@3214.03,4927.9 ; J200.112@4733.71,4885.06 J200.112@4733.71,4925.46 ; J200.98@4954.19,4885.06 J200.98@4954.19,4925.69 ; v1(5108,5201.87) 5198,5291.87 5198,5380.38 R219.2@5118,5460.38 ; J200.48@5867.57,4885.06 5867.57,4931.44 v1(5868,4931.87)
  Top Layer w25: C217.1@6018,5672.62 6070.09,5672.62 6078,5680.53 6078,5719 6098,5739 v1(6138,5739) 6155.41,5721.6 U201.1@6155.41,5683.13 ; U202.3@6585.41,5474.87 U202.4@6585.41,5583.13 6622.14,5583.13 6639.5,5600.5 C216.2@6639.5,5649 7939.13,5649 7978.13,5610 ; U209.8@8431.4,5128.11 8431.4,5180.04 C237.2@8484.9,5233.54 ; U205.8@8680.89,5126.14 8680.89,5189.53 C224.2@8724.9,5233.54
  Top Layer w29.53: C237.2@8484.9,5233.54 8484.9,5415.04 8403.46,5496.48 8300,5496.48 8250,5546.48 TP200.1@8250,5610 8330,5530 8629.94,5530 8724.9,5435.04 C223.1@8724.9,5293.54 C224.2@8724.9,5233.54
  Top Layer w50: J204.1@7969.78,5296.48 J204.3@7969.78,5396.48 7900,5466.26 7900,5531.87 7978.13,5610 TP200.1@8250,5610
  Signal Layer 1 w25: v1(5108,5201.87) 5108,4991.87 v1(5168,4931.87) 5249.88,4850 5356.17,4850 5508.53,5002.37 5541.57,5002.37 5773.88,5234.67 5840.34,5234.67 5900.66,5174.35 5900.66,5081.48 5837.63,5018.44 5837.63,4959.29 5865.05,4931.87 v1(5868,4931.87) 5868,4386.48 5960.8,4293.68 6724.49,4293.68 7110,4679.2 7110,5120 7340,5350 7969.78,5350
  Signal Layer 1 w50: J106.4@3626.46,1233.31 3653.31,1233.31 3690,1270 3690,1370 3590.59,1469.41 3590.59,2221.12 4238.62,2869.15 4238.62,3180.63 4477.15,3419.15 4477.15,3816.06 4901.08,4240 6731.87,4240 7155.94,4664.06 7155.94,5105.94 7280,5230 7903.3,5230 J204.1@7969.78,5296.48 7969.78,5350 J204.3@7969.78,5396.48
  Signal Layer 2 w50: J204.1@7969.78,5296.48 J204.3@7969.78,5396.48
  Signal Layer 3 w50: J204.1@7969.78,5296.48 J204.3@7969.78,5396.48
  Signal Layer 4 w50: J111.2@5444.68,4620.63 5404.68,4620.63 5384.45,4640.87 5384.45,5070.78 5540.92,5227.25 5540.92,5382.76 5636.03,5477.87 5860.82,5477.87 6060.82,5677.87 7983.97,5677.87 8140,5521.85 8140,5270 8100,5230 8027.39,5230 7969.78,5287.61 J204.1@7969.78,5296.48 J204.3@7969.78,5396.48
  Bottom Layer w25: v1(6138,5739) 6157,5720 8010,5720 8120,5610 TP200.1@8250,5610
  Bottom Layer w50: J104.4@3626.46,2703.38 3843.38,2703.38 3960,2820 3960,3310 4000,3350 4397.15,3350 4477.15,3430 4477.15,3816.06 4850,4188.92 6647.04,4188.92 7155.94,4697.81 7155.94,5195.94 7190,5230 7903.3,5230 J204.1@7969.78,5296.48 ; J110.2@5650.63,4620.63 5619.94,4620.63 5592.76,4647.82 5592.76,4654.79 5590.39,4657.15 5590.39,5129.83 5542.13,5178.1 5542.13,5383.97 5636.03,5477.87 5860.82,5477.87 6060.82,5677.87 7983.97,5677.87 8140,5521.85 8140,5270 8100,5230 8027.39,5230 7969.78,5287.61 J204.1@7969.78,5296.48 ; J204.3@7969.78,5396.48 J204.1@7969.78,5296.48
5Vs: C222.2 C235.2 J108.3 J109.3 J203.7 TP201.1 U205.1 U209.1 | length 7761.1
  Top Layer w20: v1(8656.4,4643.54) 8680.89,4668.03 U205.1@8680.89,4697.01 ; v1(8856.4,4643.54) 8867.89,4632.05 C222.2@8906.4,4632.05
  Top Layer w25: v1(8396.4,4693.54) 8425.96,4693.54 U209.1@8431.4,4698.98 8431.4,4637.05 C235.2@8417.89,4623.54
  Top Layer w50: TP201.1@7830,4600 7873.3,4600 J203.7@7969.78,4696.48
  Signal Layer 1 w20: v1(8656.4,4643.54) v1(8856.4,4643.54)
  Signal Layer 1 w25: v1@8396.02,4693.92 v1(8396.4,4693.54)
  Signal Layer 1 w50: J203.7@7969.78,4696.48 7873.3,4600 TP201.1@7830,4600 ; J108.3@8190.63,2010.55 8190.63,1952.98 8177.65,1940 8060,1940 8010,1990 8010,2150 8450,2590 8450,3600 8400,3650 7930,3650 7830,3750 TP201.1@7830,4600 ; J109.3@8190.63,3480.63 8190.63,3420 8170.63,3400 8079.78,3400 7770,3709.78 7770,4540 TP201.1@7830,4600
  Signal Layer 2 w50: TP201.1@7830,4600 7873.3,4600 J203.7@7969.78,4696.48
  Signal Layer 3 w50: TP201.1@7830,4600 7873.3,4600 J203.7@7969.78,4696.48
  Signal Layer 4 w50: TP201.1@7830,4600 7873.3,4600 J203.7@7969.78,4696.48
  Bottom Layer w25: v1(8396.4,4693.54) 8339.94,4750 8023.3,4750 J203.7@7969.78,4696.48 7969.78,4761.65 7988.13,4780 8360,4780 8443.58,4696.42 8630.01,4696.42 8649.27,4677.16 8656.4,4670 v1(8656.4,4643.54)
BATT_RTN: J102.1 J102.2 J102.3 R102.1 R104.1 R108.1 R112.1 R116.1 R232.1 TP103.1 | length 827
  Top Layer w20: R232.1@8857.89,4483.54 v1(8906.4,4483.54) ; v1(9166.4,4263.54) R112.1@9166.4,4307.52
  Top Layer w50: R102.1@8982.79,4311.12 R112.1@9162.79,4311.12 R108.1@9252.79,4311.12 R104.1@9342.79,4311.12
  Signal Layer 1 w20: v1(8906.4,4483.54) 8966.4,4483.54 9136.4,4313.54 9136.4,4273.54 9146.4,4263.54 v1(9166.4,4263.54)
  other v1: 9756.4,3963.54 9786.4,3983.54 9446.4,4103.54 8946.4,4360 8996.4,4360 9046.4,4360 9146.4,4360 9196.4,4360 9246.4,4360 9296.4,4360 9346.4,4360 8936.4,4443.54 9786.4,4513.54 9766.4,4543.54 9036.4,4553.54
COIL_PRI_N: C240.2 C245.1 pad.4 R247.1 R261.2 U208.3 | length 964.4
  Bottom Layer w10: pad.4@5668,4441.87 5671.87,4441.87 5810,4580 5810,4716.22 5965.88,4872.1 5965.88,4929.75 v1(5998,4961.87)
  Bottom Layer w20: v1(5998,4961.87) C240.2@5998,4998.25 6003.6,4998.25 6025.41,5020.06 R261.2@6134.38,5020.06 U208.3@6134.38,5101.01 ; R247.1@6091.63,5111.87 U208.3@6134.38,5111.87
COIL_PRI_P: pad.3 R248.1 | length 820
  Signal Layer 1 w10: v1@5943,4956.87 v1(5948,4961.87)
  Bottom Layer w10: pad.3@5668,4361.87 5619.29,4410.59 5619.29,4453.79 5650.24,4484.75 5684.75,4484.75 5792.13,4592.13 5792.13,4723.62 5948,4879.5 v1(5948,4961.87)
  Bottom Layer w20: v1(5948,4961.87) R248.1@5948,4998.25
COIL_SEC_N: C227.2 C231.1 pad.2 R229.1 R239.2 U204.3 | length 379.7
  Top Layer w12: R229.1@5924.38,4361.87 5924.38,4414.63
  Top Layer w20: pad.2@5798,4441.87 5825.25,4414.63 5924.38,4414.63 C227.2@5924.38,4321.87 ; R239.2@5908,4418.25 5981.59,4418.25 U204.3@5997.81,4434.47
COIL_SEC_P: pad.1@5798,4361.87 R230.1 | length 159.5
  Top Layer w20: pad.1@5798,4361.87 5878,4281.87 R230.1@5924.38,4281.87
Crp_1: C127.2 C129.2 C131.2 C133.2 C135.2 C137.2 C139.2 C141.2 C143.2 C145.2 pad.1@5511.81,1771.65
  other v1: 5170.56,1840.16 5200,1840 5810,1840 5840,1840 5200,1870 5230,1870 5260,1870 5750,1870.39 5780,1870 5809.5,1870.39
Crs_1: C100.1 C105.1 C108.1 C109.1 C110.1 C113.1 C114.1 C115.1 C122.1 C126.1 C128.1 C130.1 C132.1 C134.1 C136.1 C138.1 pad.1@6299.21,1771.65
  other v1: 5950,1750 6661.81,1750 5950.39,1780 6661.81,1780 5950,1810 5980,1810 6630,1810 6661.81,1810
CS: QPL1L_S.1 QPL2L_S.1 R118.2 R119.2 R120.2 R121.2 R122.2 R205.2 | length 1564.3
  Top Layer w20: 3935.04,3150 3910,3150 3908.23,3151.77 3890,3151.77 3870,3171.77 3870,3548.99 4268.52,3947.51 R205.2@4268.52,4093.89
  Top Layer w75: R121.2@3935.04,2905.51 R122.2@3935.04,3005.51 R120.2@3935.04,3105.51 3935.04,3150 R118.2@3935.04,3205.51 R119.2@3935.04,3305.51 ; QPL1L_S.1@4641.17,3102.12 QPL1L_S.1@4644.2,3102.12
  other v1: 4308.52,2200 4336.49,2230 4370,2260 4400,2289.74 4430,2320 4470,2320 4007.95,2886.85 4007.95,2926.85 4007.95,2966.85 4007.95,3006.85 4007.95,3046.85 4007.95,3086.85 4007.95,3126.85 4007.95,3166.85 4007.95,3206.85 4007.95,3246.85 4007.95,3286.85
HVBUS: C101.1 C102.1 C120.1 C121.1 QPL1H_D.1 QPL2H_D.1 R100.2 R101.2 R240.2 TP100.1 XF101.1 XF101.2 | length 3504.7
  Top Layer w20: v1(3850,4680) R240.2@3905.57,4680
  Signal Layer 1 w20: C102.1@3277.48,2172.36 2880,2569.84 2880,3082.12 2790,3172.12 2790,3916.54 3553.46,4680 v1(3850,4680)
  Bottom Layer w50: 3157.48,2156 3261.12,2156 C102.1@3277.48,2172.36
  other v1: 4050,1920 4090,1920 4130,1920 4169.47,1920 4210,1920
ISNS_PRIM_SHUNT: R201.2 R214.1 R217.2 U200.1 | length 4746.3
  Top Layer w20: v1(4228.52,4277.51) 4233.33,4277.51 4235.92,4274.91 U200.1@4268.33,4274.91 ; R201.2@4418.52,4093.89 4424.9,4093.89 v1(4448.52,4117.51) ; R217.2@6084.38,4691.87 6084.38,4685.5 6088,4681.87 v1(6088,4641.87) ; v1(6287.1,5317.69) 6287.1,5231.4 R214.1@6299.5,5219
  Signal Layer 1 w20: v1@4235.92,4274.91 4236.4,4275.38 4330.65,4275.38 4378.52,4227.51 4468.52,4227.51 4486.4,4209.64 4486.4,4155.38 v1(4448.52,4117.51)
  Signal Layer 2 w20: v1(5208,4324) 5230.13,4324 ; 5842.71,4539.73 5845.86,4539.73 5948,4641.87 v1(6088,4641.87) ; 5842.69,4539.75 5816.46,4539.75 5766.46,4489.75 5438.67,4489.75 5272.92,4324 5230.13,4324 ; v1(6287.1,5317.69) 6507.27,5317.69 6516.46,5326.87 6589.55,5326.87 6605.88,5310.55 6605.88,5287.45 6544.55,5226.13 6362.26,5226.13 6144.38,5008.25 5674.38,5008.25 5398,4731.87 5398,4491.87 5230.13,4324
  Bottom Layer w20: v1(4448.52,4117.51) 4655.01,4324 v1(5208,4324)
ISNS_PRIM_TANK: C246.1 J200.23 J200.25 R254.1 | length 148.3
  Top Layer w20: v1(6228,4981.87) 6228,5004.94 J200.25@6214.03,5018.92 J200.23@6245.52,5018.92
  Bottom Layer w20: v1(6228,4981.87) R254.1@6228,5055.85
